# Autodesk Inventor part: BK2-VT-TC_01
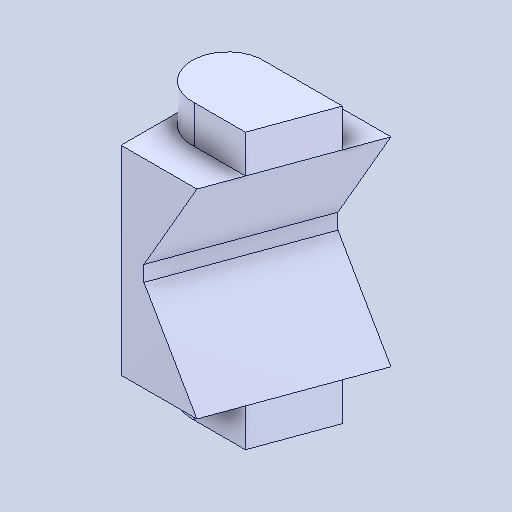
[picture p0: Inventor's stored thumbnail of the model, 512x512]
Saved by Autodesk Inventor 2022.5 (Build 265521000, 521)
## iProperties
Created: 2024-05
Part Number: BK2-VT-TC_01
Material: 一般
Document SubType Name: Modeling
Designer: ImaoCorp
Density: 1 g/cm^3
Appearance: 既定
Author: ImaoCorp
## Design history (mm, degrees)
feature "BK2-VT-TC_01"
node "ソリッド1"
